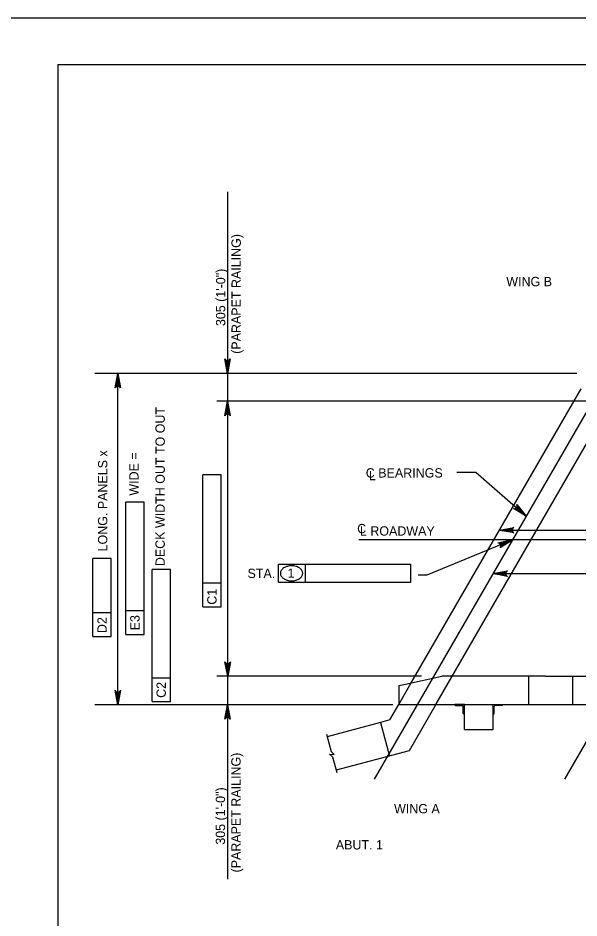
# Model space of a CAD drawing. Extents: x 638268 to 640277, y 295465 to 298435.
# Drawn here: x 639303.6 to 639484.1, y 298145.6 to 298435.5 of the extents above; entities that cross this region are included whole.
import ezdxf

# ---------------------------------------------------------------- set-up
doc = ezdxf.new("R2010")
doc.units = 0
for name, color, linetype in [('2', 7, 'Continuous'), ('3', 7, 'Continuous'), ('4', 7, 'Continuous'), ('PLT-BNDY', 7, 'Continuous')]:
    doc.layers.add(name, color=color, linetype=linetype)

msp = doc.modelspace()

# ---------------------------------------------------------------- linework, layer by layer
at = {"layer": '2'}
for p, q in [((639316.46, 297856.46), (639316.46, 298420.46)), ((639316.46, 298420.46), (640102.46, 298420.46)), ((639438.05, 298214.45), (639499.67, 298321.18)), ((639429.71, 298220.67), (639484.75, 298316.01)), ((639428.29, 298220.97), (639439.96, 298223.57)), ((639473.27, 298223.57), (639439.96, 298223.57)), ((639468, 298214.45), (639468, 298223.57)), ((639473.27, 298223.57), (639610.92, 298223.57)), ((639482.07, 298214.45), (639482.07, 298223.57)), ((639426.12, 298220.48), (639428.29, 298220.97)), ((639426.12, 298214.45), (639429.71, 298220.67)), ((639426.12, 298220.48), (639426.12, 298214.45)), ((639426.12, 298219.62), (639426.12, 298214.45)), ((639423.2, 298209.41), (639426.12, 298214.45)), ((639426.12, 298214.45), (639624.79, 298214.45)), ((639438.05, 298214.45), (639429.42, 298199.5)), ((639444.12, 298214.27), (639444.12, 298214.45)), ((639447.21, 298214.45), (639444.12, 298214.45)), ((639444.3, 298214.09), (639446.48, 298214.09)), ((639446.85, 298211.54), (639446.85, 298213.72)), ((639447.21, 298214.45), (639456.45, 298214.45)), ((639447.21, 298206.36), (639447.21, 298214.45)), ((639447.21, 298211.36), (639447.21, 298214.45)), ((639456.45, 298214.45), (639459.54, 298214.45)), ((639456.45, 298206.36), (639456.45, 298214.45)), ((639456.45, 298211.36), (639456.45, 298214.45)), ((639456.81, 298211.54), (639456.81, 298213.72)), ((639459.36, 298214.09), (639457.17, 298214.09)), ((639459.54, 298214.27), (639459.54, 298214.45)), ((639447.03, 298211.36), (639447.21, 298211.36)), ((639456.63, 298211.36), (639456.45, 298211.36)), ((639420.18, 298208.6), (639403.1, 298204.02)), ((639423.2, 298209.41), (639420.18, 298208.6)), ((639420.18, 298208.6), (639423.07, 298197.8)), ((639447.21, 298206.36), (639456.45, 298206.36)), ((639429.42, 298199.5), (639405.99, 298193.23))]:
    msp.add_line(p, q, dxfattribs=at)
for centre, radius, start, end in [((639444.3, 298214.27), 0.182, 180.0016, 270), ((639446.48, 298213.72), 0.364, 0.0016, 90), ((639457.17, 298213.72), 0.364, 90, 179.9984), ((639459.36, 298214.27), 0.182, 270, 359.9984), ((639447.03, 298211.54), 0.182, 180.0016, 270), ((639456.63, 298211.54), 0.182, 270, 359.9984)]:
    msp.add_arc(centre, radius, start, end, dxfattribs=at)
at = {"layer": '3'}
for p, q in [((639402.88, 298204.86), (639404.38, 298199.26)), ((639405.27, 298198.28), (639404.38, 298199.26)), ((639403.77, 298198.37), (639405.27, 298198.28)), ((639404.82, 298197.59), (639403.77, 298198.37)), ((639404.82, 298197.59), (639406.2, 298192.46))]:
    msp.add_line(p, q, dxfattribs=at)
at = {"layer": '4'}
for p, q in [((639371.02, 298379.52), (639371.02, 298158.13)), ((639512.19, 298353.2), (639418.17, 298190.35)), ((639483.43, 298321.03), (639328.27, 298321.03)), ((639335.67, 298214.3), (639335.67, 298321.03)), ((639490.03, 298312.06), (639367.51, 298312.06)), ((639444.74, 298289.17), (639450.86, 298289.17)), ((639450.86, 298289.17), (639467.08, 298275.06)), ((639363.01, 298245.88), (639363.01, 298288.4)), ((639368.91, 298288.4), (639363.01, 298288.4)), ((639368.91, 298245.88), (639368.91, 298288.4)), ((639338.23, 298236.98), (639338.23, 298279.5)), ((639344.13, 298279.5), (639338.23, 298279.5)), ((639344.13, 298236.98), (639344.13, 298279.5)), ((639458.48, 298270.51), (639654.17, 298270.51)), ((639705.49, 298267.4), (639413.2, 298267.4)), ((639462.66, 298267.4), (639435.18, 298256.08)), ((639327.67, 298236.32), (639327.67, 298261.37)), ((639333.57, 298261.36), (639327.67, 298261.37)), ((639333.57, 298236.32), (639333.57, 298261.36)), ((639346.69, 298215.37), (639346.69, 298257.88)), ((639352.59, 298257.88), (639346.69, 298257.88)), ((639352.59, 298215.36), (639352.59, 298257.88)), ((639387.38, 298259.61), (639429.9, 298259.61)), ((639387.38, 298253.71), (639387.38, 298259.61)), ((639396.12, 298253.71), (639396.12, 298259.61)), ((639429.9, 298259.61), (639429.9, 298253.71)), ((639435.18, 298256.08), (639432.34, 298256.08)), ((639456.38, 298256.53), (639640.13, 298256.53)), ((639368.91, 298253.44), (639363.01, 298253.45)), ((639429.9, 298253.71), (639387.38, 298253.71)), ((639515.68, 298253.16), (639479.42, 298190.35)), ((639363.01, 298245.88), (639368.91, 298245.88)), ((639333.57, 298243.88), (639327.67, 298243.88)), ((639344.13, 298244.54), (639338.23, 298244.54)), ((639338.23, 298236.98), (639344.13, 298236.98)), ((639327.67, 298236.32), (639333.57, 298236.32)), ((639352.59, 298222.92), (639346.69, 298222.93)), ((639433.46, 298223.57), (639367.51, 298223.57)), ((639424.2, 298214.3), (639328.27, 298214.3)), ((639346.69, 298215.37), (639352.59, 298215.36))]:
    msp.add_line(p, q, dxfattribs=at)
for points in [[(639371.02, 298321.03), (639370.15, 298325.69), (639370.4, 298325.33), (639370.71, 298325.15), (639371.02, 298325.09), (639371.33, 298325.15), (639371.65, 298325.33), (639371.89, 298325.69), (639371.02, 298321.03), (639371.65, 298325.33), (639371.33, 298325.15), (639371.02, 298321.03), (639371.02, 298325.09), (639370.71, 298325.15), (639371.02, 298321.03), (639370.4, 298325.33)], [(639335.67, 298321.03), (639336.55, 298316.37), (639336.3, 298316.73), (639335.98, 298316.91), (639335.67, 298316.97), (639335.36, 298316.91), (639335.05, 298316.73), (639334.8, 298316.37), (639335.67, 298321.03), (639335.05, 298316.73), (639335.36, 298316.91), (639335.67, 298321.03), (639335.67, 298316.97), (639335.98, 298316.91), (639335.67, 298321.03), (639336.3, 298316.73)], [(639371.02, 298312.06), (639371.89, 298307.4), (639371.65, 298307.76), (639371.33, 298307.94), (639371.02, 298308), (639370.71, 298307.94), (639370.4, 298307.76), (639370.15, 298307.4), (639371.02, 298312.06), (639370.4, 298307.76), (639370.71, 298307.94), (639371.02, 298312.06), (639371.02, 298308), (639371.33, 298307.94), (639371.02, 298312.06), (639371.65, 298307.76)], [(639467.08, 298275.06), (639462.99, 298277.46), (639463.42, 298277.41), (639463.77, 298277.53), (639464.01, 298277.73), (639464.18, 298278), (639464.24, 298278.36), (639464.13, 298278.78), (639467.08, 298275.06), (639464.24, 298278.36), (639464.18, 298278), (639467.08, 298275.06), (639464.01, 298277.73), (639463.77, 298277.53), (639467.08, 298275.06), (639463.42, 298277.41)], [(639458.48, 298270.51), (639463.14, 298271.38), (639462.78, 298271.13), (639462.6, 298270.82), (639462.55, 298270.51), (639462.6, 298270.2), (639462.78, 298269.88), (639463.14, 298269.64), (639458.48, 298270.51), (639462.78, 298269.88), (639462.6, 298270.2), (639458.48, 298270.51), (639462.55, 298270.51), (639462.6, 298270.82), (639458.48, 298270.51), (639462.78, 298271.13)], [(639462.66, 298267.4), (639458.68, 298264.82), (639458.92, 298265.18), (639458.97, 298265.54), (639458.9, 298265.85), (639458.73, 298266.12), (639458.44, 298266.34), (639458.01, 298266.43), (639462.66, 298267.4), (639458.44, 298266.34), (639458.73, 298266.12), (639462.66, 298267.4), (639458.9, 298265.85), (639458.97, 298265.54), (639462.66, 298267.4), (639458.92, 298265.18)], [(639456.38, 298256.53), (639461.04, 298257.4), (639460.68, 298257.15), (639460.49, 298256.84), (639460.44, 298256.53), (639460.49, 298256.22), (639460.68, 298255.9), (639461.04, 298255.66), (639456.38, 298256.53), (639460.68, 298255.9), (639460.49, 298256.22), (639456.38, 298256.53), (639460.44, 298256.53), (639460.49, 298256.84), (639456.38, 298256.53), (639460.68, 298257.15)], [(639371.06, 298223.52), (639370.18, 298228.18), (639370.43, 298227.82), (639370.75, 298227.64), (639371.06, 298227.59), (639371.37, 298227.64), (639371.68, 298227.82), (639371.93, 298228.18), (639371.06, 298223.52), (639371.68, 298227.82), (639371.37, 298227.64), (639371.06, 298223.52), (639371.06, 298227.59), (639370.75, 298227.64), (639371.06, 298223.52), (639370.43, 298227.82)], [(639335.67, 298214.3), (639334.8, 298218.96), (639335.05, 298218.6), (639335.36, 298218.42), (639335.67, 298218.36), (639335.98, 298218.42), (639336.3, 298218.6), (639336.55, 298218.96), (639335.67, 298214.3), (639336.3, 298218.6), (639335.98, 298218.42), (639335.67, 298214.3), (639335.67, 298218.36), (639335.36, 298218.42), (639335.67, 298214.3), (639335.05, 298218.6)], [(639371.02, 298214.3), (639371.89, 298209.64), (639371.65, 298210), (639371.33, 298210.18), (639371.02, 298210.24), (639370.71, 298210.18), (639370.4, 298210), (639370.15, 298209.64), (639371.02, 298214.3), (639370.4, 298210), (639370.71, 298210.18), (639371.02, 298214.3), (639371.02, 298210.24), (639371.33, 298210.18), (639371.02, 298214.3), (639371.65, 298210)]]:
    msp.add_lwpolyline(points, dxfattribs=at)
for points in [[(639335.2, 298318.19), (639336.15, 298318.19), (639335.67, 298321.03)], [(639464.53, 298276.63), (639465.17, 298277.37), (639467.08, 298275.06)], [(639461.43, 298271), (639461.43, 298270.02), (639458.48, 298270.51)], [(639459.85, 298266.76), (639460.21, 298265.88), (639462.65, 298267.4)], [(639459.33, 298257.02), (639459.33, 298256.04), (639456.38, 298256.53)], [(639335.2, 298217.14), (639336.15, 298217.14), (639335.67, 298214.3)]]:
    msp.add_lwpolyline(points, close=True, dxfattribs=at)
for centre, radius, start, end in [((639389.71, 298256.65), 1.68, 148.5507, 180), ((639390.62, 298256.09), 2.75, 124.109, 148.5507), ((639391.22, 298255.2), 3.82, 105.6708, 124.109), ((639391.61, 298253.8), 5.27, 90, 105.6708), ((639391.61, 298253.8), 5.27, 74.3292, 90), ((639392, 298255.2), 3.82, 55.891, 74.3292), ((639392.6, 298256.09), 2.75, 31.4493, 55.891), ((639393.52, 298256.65), 1.68, 0, 31.4493), ((639389.71, 298256.65), 1.68, 180, 211.4493), ((639390.62, 298257.21), 2.75, 211.4493, 235.891), ((639391.22, 298258.09), 3.82, 235.891, 254.3292), ((639391.61, 298259.49), 5.27, 254.3292, 270), ((639391.61, 298259.49), 5.27, 270, 285.6708), ((639392, 298258.09), 3.82, 285.6708, 304.109), ((639392.6, 298257.21), 2.75, 304.109, 328.5507), ((639393.52, 298256.65), 1.68, 328.5507, 0)]:
    msp.add_arc(centre, radius, start, end, dxfattribs=at)
at = {"layer": 'PLT-BNDY'}
msp.add_lwpolyline([(639276.46, 298435.46), (640117.46, 298435.46), (640117.46, 297841.46), (639276.46, 297841.46)], close=True, dxfattribs=at)

# ---------------------------------------------------------------- texts
at = {"layer": '4'}
for s, rotation, p in [('(PARAPET RAILING)', 90, (639375.27, 298327.33)), ('305 (1\'-0")', 90, (639370.27, 298336.26)), ('DECK WIDTH OUT TO OUT', 90, (639350.81, 298258.95)), ('LONG. PANELS x', 90, (639332.32, 298263.7)), ('WIDE =', 90, (639342.36, 298281.65)), ('C1', 89.9382, (639367.46, 298246.53)), ('E3', 89.9382, (639342.68, 298238.29)), ('D2', 89.9382, (639332.12, 298237.4)), ('C2', 89.9382, (639351.14, 298216.54)), ('(PARAPET RAILING)', 90, (639375.2, 298160.32)), ('305 (1\'-0")', 90, (639370.2, 298169.25))]:
    msp.add_text(s, height=3, rotation=rotation, dxfattribs=at).set_placement(p)
for s, p in [('WING B', (639460.7, 298349.09)), ('C BEARINGS', (639415.49, 298287.48)), ('L', (639416.49, 298286.63)), ('C', (639412.71, 298269.54)), ('L ROADWAY', (639413.6, 298268.78)), ('STA.', (639377.42, 298255.13)), ('1', (639390.31, 298255.19)), ('WING A', (639424.58, 298179.35)), ('ABUT. 1', (639405.84, 298167.72))]:
    msp.add_text(s, height=3, dxfattribs=at).set_placement(p)

doc.saveas('drawing.dxf')
